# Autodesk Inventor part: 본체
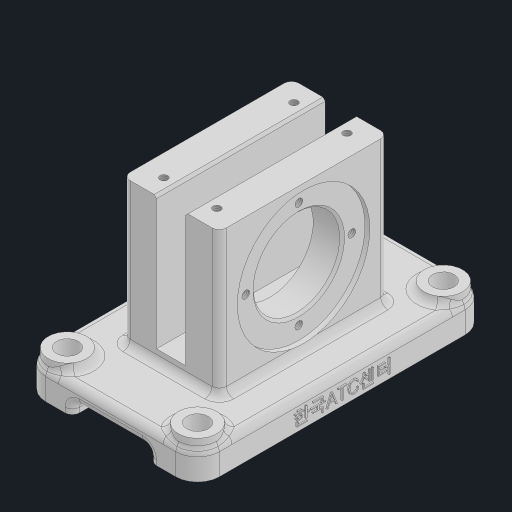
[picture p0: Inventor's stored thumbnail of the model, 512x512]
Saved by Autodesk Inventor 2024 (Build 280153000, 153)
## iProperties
Created: 2025-04
Part Number: 본체
Material: 일반
Document SubType Name: Modeling
Designer: kh_501
Density: 1 g/cm^3
Appearance: 기본값
Author: kh_501
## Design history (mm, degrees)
sketch "스케치1"
  geometry: L1 (-36, 60)-(36, 60); L2 (36, 60)-(36, -60); L3 (36, -60)-(-36, -60); L4 (-36, -60)-(-36, 60); L5 (-36, 60)-(36, -60); L6 (36, 60)-(-36, -60); 1 further point
  constraints: 12 end point, 2 midpoint, 2 parallel, 1 horizontal, 1 perpendicular
  dimensions: "d0" = 120 distance of L1.end L2.end; "d1" = 72 distance of L2.end L3.end
extrude "돌출1" new body sketch "스케치1" distance "d2" = 12; taper "d3" = 0 deg
fillet "모깎기1" dims "d4" = 9
sketch "스케치2"
  geometry: L1 (12, -51)-(12, 51) reference; L2 (12, 35)-(72, 35); L3 (72, 35)-(72, -35); L4 (72, -35)-(12, -35); L5 (12, -35)-(12, 35); L6 (0, -51)-(0, 51) reference; 3 further points
  constraints: 8 end point, 2 parallel, 1 horizontal, 1 horizontal alignment, 1 midpoint, 1 perpendicular, 1 point on line
  dimensions: "d5" = 70 distance of L2.end L3.end; "d6" = 72 distance between parallel lines of L6 L3
extrude "돌출2" join sketch "스케치2" stored distance "d7" = 40; taper "d8" = 0 deg
sketch "스케치3"
  geometry: L1 (0, 0)-(54, 0) reference; L2 (11, 0)-(43, 0); L3 (43, 0)-(43, 5); L4 (43, 5)-(11, 5); L5 (11, 5)-(11, 0); 4 further points
  constraints: 8 end point, 2 midpoint, 2 parallel, 1 horizontal, 1 perpendicular, 1 point on line, 1 vertical alignment
  dimensions: "d9" = 32 distance of L3.end L4.end; "d10" = 5 distance of L2.end L3.end
extrude "돌출3" cut sketch "스케치3" extent not by distance; stored distance "d11" = 0; taper "d12" = 0 deg
sketch "스케치4"
  geometry: L1 (40, 60)-(0, 60) reference; L2 (14, 60)-(26, 60); L3 (26, 60)-(26, 5); L4 (26, 5)-(14, 5); L5 (14, 5)-(14, 60); 4 further points
  constraints: 8 end point, 2 midpoint, 2 parallel, 1 horizontal, 1 perpendicular, 1 point on line, 1 vertical alignment
  dimensions: "d13" = 12 distance between parallel lines of L5 L3; "d14" = 55 distance between parallel lines of L1 L4
extrude "돌출4" cut sketch "스케치4" extent not by distance; stored distance "d15" = 0; taper "d16" = 0 deg
sketch "스케치5"
  geometry: L1 (-51, 0)-(51, 0) reference; C1 r 17 at (0, 42); 2 further points
  constraints: 1 centre point, 1 midpoint, 1 vertical alignment
  dimensions: "d17" = 34 diameter of C1; "d18" = 42 distance from line of L1 C1.centre
extrude "돌출5" join sketch "스케치5" distance "d19" = 7; taper "d20" = 0 deg
sketch "스케치6"
  geometry: L1 (-27, 59)-(-27, 25) reference; L2 (20, 12)-(20, 72) reference; L3 (-27, 42)-(20, 42); L4 (-27, 53)-(-11, 53); L5 (-11, 53)-(-11, 57); L6 (-11, 57)-(-6, 57); L7 (-6, 72)-(-6, 17) reference; L8 (6, 17)-(6, 72) reference; L9 (6, 60)-(18, 60); L10 (18, 60)-(18, 69.5); L11 (18, 69.5)-(20, 69.5); 3 further points
  constraints: 14 end point, 4 perpendicular, 4 point on line, 2 horizontal, 2 midpoint
  dimensions: "d21" = 22 diameter of L4 L3; "d22" = 30 diameter of L6 L3; "d23" = 36 diameter of L9 L3; "d24" = 55 diameter of L11 L3; "d25" = 2 distance of L10.end L11.end; "d26" = 5 distance of L5.end L6.end
revolve "회전1" sketch "스케치6" stored, may be unused: angle "d27" = 90 deg
chamfer "모따기1" distance "d28" = 1; stored, may be unused: second distance "d29" = 2, angle "d30" = 45 deg
sketch "스케치7"
  geometry: L1 (-20, -35)-(-20, 35) reference; L2 (-20, 35)-(20, 35) reference; L3 (20, 35)-(20, -35) reference; L4 (20, -35)-(-20, -35) reference; L5 (-36, 51)-(-36, -51) reference; L6 (-27, -60)-(27, -60) reference; L7 (36, -51)-(36, 51) reference; L8 (27, 60)-(-27, 60) reference; C1 r 8 at (-27, 51); C2 r 8 at (27, 51); C3 r 8 at (27, -51); C4 r 8 at (-27, -51); A1 r 9 centre (-27, 51) between (-27, 60) and (-36, 51) reference; A2 r 9 centre (-27, -51) between (-36, -51) and (-27, -60) reference; A3 r 9 centre (27, -51) between (27, -60) and (36, -51) reference; A4 r 9 centre (27, 51) between (36, 51) and (27, 60) reference; 1 further point
  constraints: 4 centre point, 4 coincident
  dimensions: "d31" = 16 diameter of C1; "d32" = 16 diameter of C2; "d33" = 16 diameter of C3; "d34" = 16 diameter of C4
extrude "돌출6" join sketch "스케치7" distance "d35" = 3; taper "d36" = 0 deg
sketch "스케치8"
  geometry: C1 r 8 at (0, 0) reference; C2 r 8 at (-54, 0) reference; C3 r 8 at (-54, -102) reference; C4 r 8 at (0, -102) reference; 5 further points
  constraints: 4 coincident
hole "구멍1" sketch "스케치8" at (0, 0), (-54, 0), (-54, -102), (0, -102) diameter "d37" = 9; stored, may be unused: countersink angle "d41" = 90 deg, drill point angle "d43" = 0 deg; dims "d38" = 15, "d39" = 14, "d40" = 4, "d42" = 17.1
sketch "스케치9" dims "d44" = 44
  geometry: C1 r 27.5 at (0, 0) reference; 3 further points
  constraints: 2 vertical alignment, 1 coincident, 2 other
hole "구멍2" sketch "스케치9" at (0, 22) diameter "d45" = 3.242; stored, may be unused: countersink angle "d49" = 90 deg, drill point angle "d51" = 118 deg; dims "d46" = 8, "d47" = 4, "d48" = 2, "d50" = 10
sketch "스케치10"
  geometry: L1 (9, 62)-(31, 62); L2 (31, 62)-(31, 8); L3 (31, 8)-(9, 8); L4 (9, 8)-(9, 62); L5 (9, 62)-(31, 8); L6 (31, 62)-(9, 8); 5 further points
  constraints: 12 end point, 4 coincident, 2 midpoint, 2 parallel, 1 horizontal, 1 perpendicular
  dimensions: "d55" = 54 distance of L1.end L2.end; "d56" = 22 distance of L2.end L3.end
hole "구멍3" sketch "스케치10" at (31, 8), (31, 62), (9, 62), (9, 8) diameter "d57" = 3.242; stored, may be unused: countersink angle "d61" = 90 deg, drill point angle "d63" = 118 deg; dims "d58" = 8, "d59" = 4, "d60" = 2, "d62" = 10
sketch "스케치11" dims "d0" = 120, "d1" = 72
  geometry: L1 (0, 0)-(102, 0) reference; 3 further points
  constraints: 1 midpoint, 1 vertical alignment, 1 other
  dimensions: "d64" = 5 distance from line of L1 point (51, 5)
feature "엠보싱1" sketch "스케치11" dims "d0" = 120, "d1" = 72, "d7" = 40, "d8" = 0, "d65" = 0.5, "d66" = 0
fillet "모깎기3" dims "d68" = 3
fillet "모깎기4" dims "d69" = 3
fillet "모깎기5" dims "d70" = 3
fillet "모깎기6" dims "d71" = 3
fillet "모깎기7" dims "d72" = 3
node "솔리드1"
pattern_circular "원형 패턴1" dims angle "d53" = 360 deg
node "투영된 루프1"
node "투영된 루프2"
node "투영된 루프3"
node "투영된 루프4"
node "투영된 루프5"
feature "A9D066F2-1C7D-4E18-AEED-F7BC21143FA4" dims "d37" = 9, "d38" = 15, "d39" = 14, "d40" = 4, "d41" = 90 deg, "d42" = 17.1, "d43" = 0
